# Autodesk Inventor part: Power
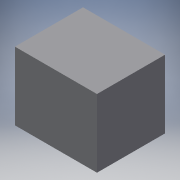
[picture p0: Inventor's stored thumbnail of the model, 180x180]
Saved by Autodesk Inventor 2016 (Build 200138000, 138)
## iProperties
Created: 2016-07
Part Number: Power
Material: Generic
Document SubType Name: Modeling
Designer: jose
Density: 1 g/cm^3
Appearance: Default
Author: jose
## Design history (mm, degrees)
sketch "Sketch1"
  geometry: L1 (0, -3.106)-(-8.661, -3.106); L2 (-8.661, -3.106)-(-8.661, 4.082); L3 (-8.661, 4.082)-(0, 4.082); L4 (0, 4.082)-(0, -3.106); L5 (0, 24.212)-(0, 26.688) reference; 1 further point
  constraints: 8 end point, 2 parallel, 1 horizontal, 1 perpendicular
  dimensions: "d0" = 8.661 distance of L1.start L1.end; "d1" = 7.188 distance of L1.end L2.end; "d2" = 29.794 distance from line of L5.end L1
extrude "Extrusion1" new body sketch "Sketch1" distance "d3" = 7.1882; taper "d4" = 0 deg
body "Solid1"
node "Reference1"
